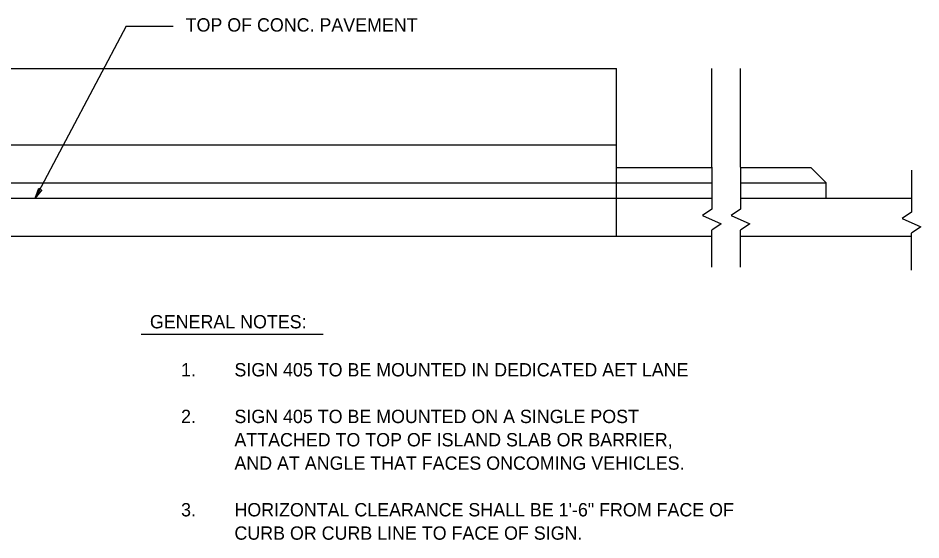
# Model space of a CAD drawing. Extents: x -63400 to -62632, y -1624834 to -1624417.
# Drawn here: x -62962.7 to -62773.2, y -1624712.6 to -1624603 of the extents above; entities that cross this region are included whole.
import ezdxf

# ---------------------------------------------------------------- set-up
doc = ezdxf.new("R2010")
doc.units = 0
for name, color, linetype in [('21', 7, 'Continuous'), ('52', 7, 'Continuous'), ('LeaderLine_dp', 7, 'Continuous'), ('TextLabel', 7, 'Continuous'), ('TextNotes', 7, 'Continuous')]:
    doc.layers.add(name, color=color, linetype=linetype)

# ---------------------------------------------------------------- blocks, each defined once
blk = doc.blocks.new('BREAK2')
at = {"layer": '21'}
for p, q in [((0.283, 0.654), (-0.283, -0.653)), ((0.738, 0), (0.283, 0.654)), ((-3.324, 0), (-0.737, 0)), ((-0.283, -0.653), (-0.737, 0)), ((3.67, 0), (0.738, 0))]:
    blk.add_line(p, q, dxfattribs=at)
blk = doc.blocks.new('T52')
at = {"layer": '52'}
blk.add_lwpolyline([(0, 0), (-0.146, -0.023), (-0.135, 0.002), (-0.145, 0.028)], close=True, dxfattribs=at)

msp = doc.modelspace()

# ---------------------------------------------------------------- linework, layer by layer
at = {"layer": '21'}
for p, q in [((-63217.14, -1624613.63), (-62837.14, -1624613.63)), ((-62837.14, -1624648.83), (-62837.14, -1624613.63)), ((-62817.14, -1624634.35), (-62817.14, -1624613.63)), ((-62811.14, -1624634.35), (-62811.14, -1624613.63)), ((-63129.14, -1624629.63), (-62837.14, -1624629.63)), ((-62837.14, -1624634.43), (-62817.14, -1624634.43)), ((-62811.14, -1624634.43), (-62796.34, -1624634.43)), ((-62793.14, -1624637.63), (-62796.34, -1624634.43)), ((-63201.14, -1624637.63), (-62837.14, -1624637.63)), ((-62837.14, -1624637.63), (-62817.14, -1624637.63)), ((-62811.14, -1624637.63), (-62793.14, -1624637.63)), ((-62793.14, -1624640.83), (-62793.14, -1624637.63)), ((-63295.75, -1624640.83), (-62837.14, -1624640.83)), ((-62837.14, -1624640.83), (-62817.14, -1624640.83)), ((-62811.14, -1624640.83), (-62775.14, -1624640.83)), ((-63331.75, -1624648.83), (-62817.14, -1624648.83)), ((-62811.14, -1624648.83), (-62775.14, -1624648.83))]:
    msp.add_line(p, q, dxfattribs=at)
at = {"layer": 'LeaderLine_dp'}
for q in [(-62959.11, -1624640.83), (-62930.21, -1624604.74)]:
    msp.add_line((-62940.02, -1624604.74), q, dxfattribs=at)
at = {"layer": 'TextNotes'}
msp.add_line((-62936.87, -1624669.39), (-62898.68, -1624669.39), dxfattribs=at)

# ---------------------------------------------------------------- block references
at = {"layer": '21', "xscale": 3, "yscale": 3, "rotation": 90}
for p in [(-62817.14, -1624645.36), (-62811.14, -1624645.36), (-62775.2, -1624646)]:
    msp.add_blockref('BREAK2', p, dxfattribs=at)
at = {"layer": 'LeaderLine_dp', "xscale": 15.000000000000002, "yscale": 15.000000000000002, "rotation": -117.86604852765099}
msp.add_blockref('T52', (-62959.11, -1624640.83), dxfattribs=at)

# ---------------------------------------------------------------- texts
at = {"layer": 'TextLabel'}
msp.add_text('TOP OF CONC. PAVEMENT', height=2.8, dxfattribs=at).set_placement((-62927.56, -1624605.86))
at = {"layer": 'TextNotes'}
for s, p in [('GENERAL NOTES:', (-62935.06, -1624668.2)), ('1.', (-62928.52, -1624678.29)), ('SIGN 405 TO BE MOUNTED IN DEDICATED AET LANE', (-62917.32, -1624678.29)), ('2.', (-62928.52, -1624688.09)), ('SIGN 405 TO BE MOUNTED ON A SINGLE POST', (-62917.32, -1624688.09)), ('ATTACHED TO TOP OF ISLAND SLAB OR BARRIER,', (-62917.32, -1624692.99)), ('AND AT ANGLE THAT FACES ONCOMING VEHICLES.', (-62917.32, -1624697.89)), ('3.', (-62928.52, -1624707.69)), ('HORIZONTAL CLEARANCE SHALL BE 1\'-6" FROM FACE OF', (-62917.32, -1624707.69)), ('CURB OR CURB LINE TO FACE OF SIGN.', (-62917.32, -1624712.59))]:
    msp.add_text(s, height=2.8, dxfattribs=at).set_placement(p)

doc.saveas('drawing.dxf')
